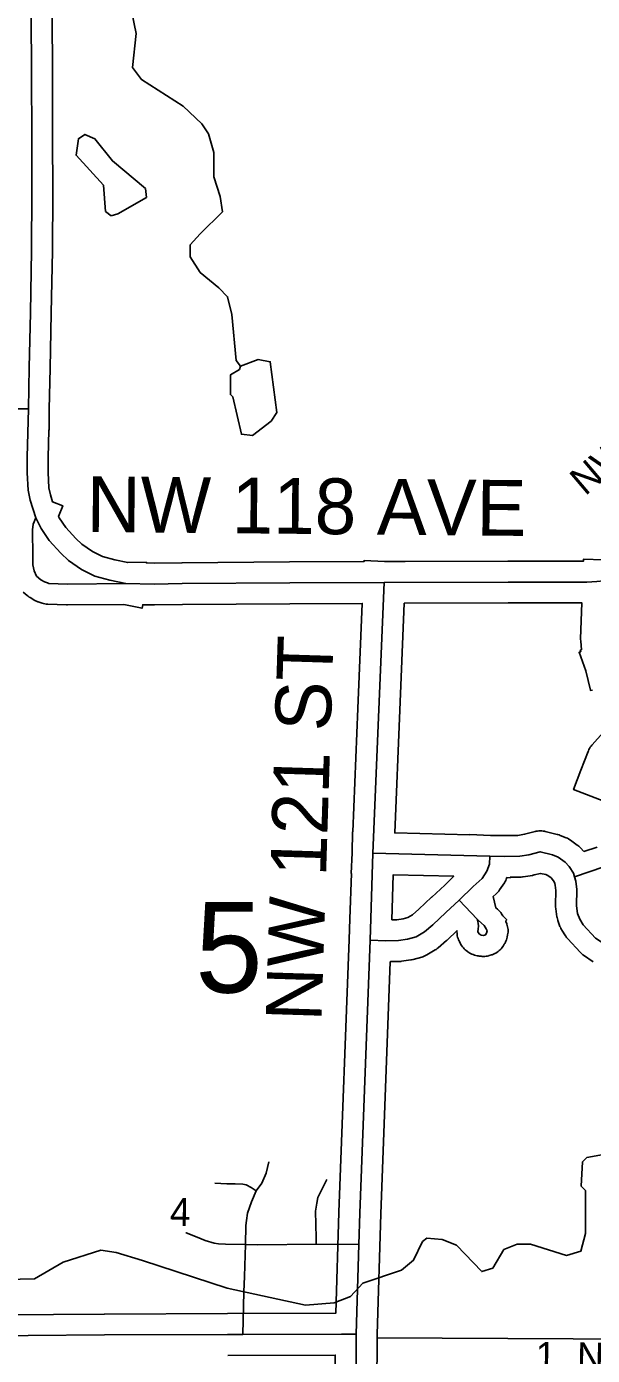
# Model space of a CAD drawing. Extents: x -1403959 to 81668, y -1400582 to 11018.
# Drawn here: x 6320.4 to 6398.9, y 9402.8 to 9587.1 of the extents above; entities that cross this region are included whole.
import ezdxf

# ---------------------------------------------------------------- set-up
doc = ezdxf.new("R2010")
doc.units = 0
for name, color, linetype in [('tdCiCityDivCarto', 7, 'Continuous'), ('tdCiCoBndryTxt', 7, 'Continuous'), ('tdCiMapFrame', 7, 'Continuous'), ('tdCiSectLine', 7, 'Continuous'), ('tdCoCityStreetMajor', 7, 'Continuous'), ('tdCoSectLinePart', 7, 'Continuous'), ('tdCoSectNmbr', 7, 'Continuous'), ('tdCoSurfBitum', 7, 'Continuous')]:
    doc.layers.add(name, color=color, linetype=linetype)

msp = doc.modelspace()

# ---------------------------------------------------------------- linework, layer by layer
at = {"layer": 'tdCiCityDivCarto'}
for points in [[(6350.39, 9405.67), (6350.55, 9411.6), (6350.62, 9413.72), (6350.76, 9418.15), (6350.8, 9420.78), (6350.9, 9421.49), (6351.06, 9422.48), (6351.59, 9424.08), (6352.27, 9425.6), (6353.04, 9426.67), (6353.65, 9428.03), (6354.01, 9429.62)], [(6346.51, 9426.68), (6348.18, 9426.59), (6349.35, 9426.56), (6350.39, 9426.53), (6350.85, 9426.41), (6351.56, 9426.08), (6352.27, 9425.6)], [(6360.57, 9418.2), (6360.56, 9419.07), (6360.5, 9422.79), (6360.66, 9423.88), (6360.82, 9424.68), (6361.21, 9425.5), (6362.06, 9427.17)], [(6342.5, 9419.79), (6342.53, 9419.78)], [(6342.53, 9419.78), (6344.05, 9419.17), (6345.18, 9418.72), (6346.42, 9418.34), (6347.03, 9418.25), (6348.02, 9418.18), (6350.76, 9418.15), (6352.5, 9418.11), (6360.57, 9418.2), (6366.5, 9418.14)], [(6366.5, 9418.14), (6366.5, 9418.14)]]:
    msp.add_lwpolyline(points, dxfattribs=at)
at = {"layer": 'tdCiCoBndryTxt'}
for points in [[(6320.66, 9534.06), (6320.78, 9539.8), (6320.94, 9547.4), (6321.1, 9556.04), (6321.15, 9564.12), (6321.13, 9571.78), (6321.08, 9580.54), (6321.07, 9588.81), (6321.02, 9596.89), (6321, 9605.18), (6320.94, 9612.41), (6320.93, 9620.6), (6320.88, 9625.81)], [(6283.73, 9534.18), (6285.98, 9534.14), (6290.69, 9534.12), (6295.74, 9534.12), (6299.22, 9534.12), (6307.92, 9534.1), (6318.4, 9534.08), (6320.66, 9534.06)], [(6334.16, 9509.85), (6331.96, 9510.31), (6329.88, 9510.87), (6328.05, 9511.81), (6326.25, 9513.05), (6325.18, 9514.07), (6323.56, 9515.82), (6322.44, 9517.47), (6321.68, 9518.94), (6320.9, 9521.4), (6320.62, 9522.78), (6320.52, 9525.2), (6320.52, 9527.36), (6320.66, 9534.06)], [(6370, 9510), (6387.18, 9510.05), (6398.08, 9510.05), (6399.48, 9510.15), (6400.45, 9510.23), (6401.63, 9510.33)], [(6334.16, 9509.85), (6338.12, 9509.77), (6342, 9509.84), (6356.9, 9509.95), (6370, 9510)], [(6365.81, 9287.33), (6365.81, 9288.16), (6365.85, 9307.72), (6365.85, 9307.83), (6365.94, 9330.42), (6365.96, 9349.37), (6365.95, 9356.26), (6365.95, 9356.34), (6365.95, 9356.35), (6365.95, 9356.43), (6366.01, 9382.59), (6366.13, 9405.71), (6366.5, 9418.14), (6366.63, 9422.52), (6368.05, 9460.36), (6368.45, 9472.42), (6369.27, 9492.38), (6370, 9510)], [(6368.05, 9460.36), (6370.21, 9460.29), (6371.99, 9460.31), (6373.24, 9460.5), (6374.45, 9460.83), (6375.61, 9461.52), (6376.77, 9462.51), (6378.57, 9464.22), (6380.4, 9465.91), (6382.36, 9467.83), (6383.59, 9468.95), (6384.25, 9469.95), (6384.61, 9470.92), (6384.66, 9472.01)], [(6368.45, 9472.42), (6384.66, 9472.01)], [(6384.66, 9472.01), (6386.65, 9471.99), (6388.8, 9472.01), (6390.08, 9472.23), (6391.65, 9472.63), (6393.32, 9472.23), (6394.13, 9471.9), (6395.08, 9471.2), (6395.65, 9470.58), (6396.25, 9469.68), (6396.41, 9469.15), (6400.46, 9470.53)], [(6396.41, 9469.15), (6396.58, 9468.58), (6396.73, 9467.39), (6396.66, 9465.15), (6396.82, 9464.07), (6397.11, 9463.29), (6397.59, 9462.52), (6399.3, 9460.66), (6400.62, 9459.75), (6401.35, 9459.47), (6402.36, 9459.25), (6405.48, 9459.21), (6413.56, 9458.89), (6425.02, 9458.71), (6427.02, 9458.71)], [(6382.9, 9463.28), (6383.03, 9462.75), (6383.06, 9462.3), (6383.04, 9461.93), (6382.99, 9461.54), (6383.16, 9461.23), (6383.44, 9461.05), (6383.76, 9461.02), (6384.05, 9461.1), (6384.21, 9461.36), (6384.27, 9461.66), (6384.16, 9461.96), (6383.86, 9462.43), (6383.09, 9463.08), (6382.9, 9463.28), (6380.4, 9465.91)], [(6253.17, 9405.01), (6257.36, 9405.04), (6266.29, 9405.11), (6287.87, 9405.26), (6310.01, 9405.46), (6331.21, 9405.6), (6348.29, 9405.66), (6350.39, 9405.67), (6364.08, 9405.73), (6366.13, 9405.71)]]:
    msp.add_lwpolyline(points, dxfattribs=at)
at = {"layer": 'tdCiMapFrame'}
for points in [[(6323.31, 9509.94), (6322.92, 9510.06), (6322.39, 9510.38), (6321.81, 9510.88), (6321.45, 9511.59), (6321.27, 9512.44), (6321.27, 9513.59), (6321.23, 9517.29), (6321.35, 9518.06), (6321.68, 9518.94)], [(6323.31, 9509.94), (6323.49, 9509.87), (6326.07, 9509.77), (6334.16, 9509.85)]]:
    msp.add_lwpolyline(points, dxfattribs=at)
at = {"layer": 'tdCiSectLine'}
for points in [[(6323.97, 9588.82), (6323.99, 9580.55), (6324.03, 9571.8), (6324.03, 9571.79), (6324.05, 9564.12), (6324.05, 9564.12), (6324.05, 9564.1), (6324, 9556.02), (6324, 9555.98), (6323.84, 9547.35), (6323.84, 9547.34), (6323.68, 9539.74), (6323.68, 9539.74), (6323.56, 9534.02), (6323.54, 9531.14), (6323.5, 9531.14), (6323.42, 9527.33), (6323.42, 9525.26), (6323.51, 9523.13), (6323.71, 9522.14), (6324.02, 9521.17), (6325.42, 9520.64), (6324.85, 9519.13), (6324.94, 9518.96), (6325.84, 9517.63), (6327.25, 9516.11), (6328.08, 9515.31), (6329.54, 9514.3), (6330.93, 9513.59), (6332.63, 9513.14), (6334.45, 9512.76), (6337.04, 9512.79), (6337.04, 9512.7), (6338.13, 9512.68), (6341.96, 9512.74), (6341.98, 9512.74), (6356.88, 9512.85), (6356.89, 9512.85), (6367.09, 9512.89), (6367.09, 9512.89), (6367.21, 9512.89), (6367.22, 9513.02), (6370.05, 9512.9), (6372.89, 9512.91), (6372.89, 9512.91), (6387.18, 9512.95), (6387.18, 9512.95), (6397.65, 9512.95), (6397.66, 9513.24), (6400.38, 9513.14)], [(6309.99, 9408.36), (6331.19, 9408.5), (6331.2, 9408.5), (6348.27, 9408.56), (6363.24, 9408.62), (6363.24, 9408.63), (6363.31, 9408.63), (6363.73, 9422.61), (6363.73, 9422.63), (6365.15, 9460.46), (6365.25, 9463.35), (6365.25, 9463.35), (6365.46, 9469.63), (6365.44, 9469.64), (6365.55, 9472.51), (6365.62, 9475.39), (6365.65, 9475.39), (6365.65, 9475.41), (6365.67, 9475.41), (6366.37, 9492.49), (6366.37, 9492.49), (6366.97, 9507.08), (6356.91, 9507.04), (6342.04, 9506.94), (6338.17, 9506.87), (6338.12, 9506.87), (6338.06, 9506.87), (6336.52, 9506.9), (6336.42, 9506.42), (6333.88, 9506.95), (6326.1, 9506.87), (6326.07, 9506.87), (6325.96, 9506.87), (6323.38, 9506.97), (6323.3, 9506.98), (6323.11, 9507), (6322.93, 9507.03), (6322.74, 9507.07), (6322.58, 9507.12), (6322, 9507.31), (6321.99, 9507.32), (6321.81, 9507.38), (6321.64, 9507.46), (6321.47, 9507.55), (6321.44, 9507.57), (6320.9, 9507.89), (6320.78, 9507.97), (6320.62, 9508.08), (6320.51, 9508.17), (6319.93, 9508.66)], [(6398.9, 9495.07), (6398.66, 9495.01), (6398.65, 9495.05), (6398.6, 9495.04), (6397.95, 9497.72), (6397.03, 9500.31), (6397.25, 9500.39), (6397.19, 9500.62), (6397.35, 9500.66), (6397.25, 9501.83), (6397.25, 9501.88), (6397.24, 9502.07), (6397.24, 9502.18), (6397.43, 9507.15), (6387.19, 9507.15), (6372.78, 9507.1), (6372.17, 9492.26), (6371.47, 9475.24), (6381.88, 9474.99), (6381.88, 9475.04), (6384.74, 9474.91), (6386.65, 9474.89), (6388.55, 9474.91), (6389.48, 9475.07), (6390.93, 9475.44), (6391.08, 9475.48), (6391.27, 9475.51), (6391.46, 9475.53), (6391.65, 9475.53), (6391.84, 9475.53), (6392.03, 9475.51), (6392.22, 9475.48), (6392.33, 9475.45), (6393.99, 9475.05), (6394.07, 9475.03), (6394.25, 9474.98), (6394.42, 9474.91), (6395.23, 9474.58), (6395.24, 9474.58), (6395.41, 9474.5), (6395.58, 9474.41), (6395.74, 9474.31), (6395.83, 9474.25), (6396.78, 9473.55), (6396.85, 9473.51), (6396.99, 9473.39), (6397.13, 9473.26), (6397.21, 9473.17), (6397.7, 9472.65)], [(6401.68, 9479.18), (6396.26, 9481.26), (6397.29, 9483.97), (6398.29, 9486.56), (6398.31, 9486.63), (6398.39, 9486.81), (6398.48, 9486.98), (6398.58, 9487.14), (6398.69, 9487.29), (6398.81, 9487.44), (6398.82, 9487.45), (6401.88, 9490.9)], [(6397.7, 9472.65), (6399.52, 9473.27)], [(6398.97, 9457.37), (6397.65, 9458.27), (6397.54, 9458.36), (6397.39, 9458.48), (6397.25, 9458.61), (6397.17, 9458.69), (6395.45, 9460.55), (6395.4, 9460.61), (6395.28, 9460.76), (6395.17, 9460.91), (6395.13, 9460.98), (6394.65, 9461.75), (6394.6, 9461.83), (6394.51, 9462), (6394.43, 9462.17), (6394.38, 9462.29), (6394.1, 9463.08), (6394.07, 9463.14), (6394.02, 9463.32), (6393.98, 9463.51), (6393.96, 9463.63), (6393.79, 9464.7), (6393.78, 9464.77), (6393.76, 9464.96), (6393.75, 9465.15), (6393.76, 9465.24), (6393.82, 9467.26), (6393.73, 9467.98), (6393.65, 9468.25), (6393.58, 9468.45), (6393.36, 9468.79), (6393.14, 9469.02), (6392.7, 9469.34), (6392.42, 9469.46), (6391.67, 9469.64), (6390.81, 9469.42), (6390.65, 9469.38), (6390.56, 9469.36), (6389.28, 9469.15), (6389.18, 9469.14), (6388.99, 9469.12), (6388.84, 9469.11), (6387.49, 9469.1), (6387.49, 9469.04), (6387.01, 9469.05), (6386.98, 9468.95), (6386.93, 9468.84), (6386.86, 9468.67), (6386.77, 9468.5), (6386.67, 9468.34), (6386, 9467.34), (6386, 9467.34), (6385.89, 9467.19), (6385.77, 9467.04), (6385.64, 9466.9), (6385.55, 9466.82), (6385.11, 9466.41), (6385.5, 9464.84), (6385.73, 9464.65), (6385.77, 9464.61), (6385.91, 9464.48), (6386.04, 9464.34), (6386.16, 9464.2), (6386.27, 9464.04), (6386.29, 9464.01), (6386.46, 9463.75), (6387, 9463.18), (6386.85, 9463.05), (6386.89, 9462.94), (6387, 9462.64), (6387.02, 9462.59), (6387.07, 9462.41), (6387.12, 9462.23), (6387.15, 9462.04), (6387.17, 9461.85), (6387.17, 9461.66), (6387.17, 9461.47), (6387.15, 9461.28), (6387.12, 9461.09), (6387.12, 9461.09), (6387.06, 9460.79), (6387.01, 9460.61), (6386.96, 9460.43), (6386.89, 9460.25), (6386.81, 9460.08), (6386.72, 9459.91), (6386.66, 9459.81), (6386.49, 9459.54), (6386.46, 9459.49), (6386.35, 9459.34), (6386.23, 9459.19), (6386.1, 9459.05), (6385.96, 9458.92), (6385.81, 9458.8), (6385.66, 9458.69), (6385.5, 9458.59), (6385.33, 9458.5), (6385.16, 9458.42), (6384.98, 9458.35), (6384.86, 9458.32), (6384.57, 9458.23), (6384.51, 9458.22), (6384.33, 9458.17), (6384.14, 9458.14), (6383.95, 9458.12), (6383.76, 9458.12), (6383.57, 9458.12), (6383.44, 9458.13), (6383.12, 9458.17), (6383.06, 9458.18), (6382.88, 9458.21), (6382.69, 9458.25), (6382.51, 9458.31), (6382.33, 9458.37), (6382.16, 9458.45), (6381.99, 9458.54), (6381.9, 9458.59), (6381.62, 9458.77), (6381.54, 9458.82), (6381.39, 9458.93), (6381.24, 9459.05), (6381.1, 9459.18), (6380.98, 9459.32), (6380.85, 9459.47), (6380.74, 9459.62), (6380.64, 9459.78), (6380.6, 9459.86), (6380.44, 9460.17), (6380.39, 9460.26), (6380.31, 9460.43), (6380.24, 9460.61), (6380.19, 9460.79), (6380.14, 9460.97), (6380.11, 9461.16), (6380.1, 9461.35), (6380.09, 9461.54), (6380.09, 9461.67), (6378.76, 9460.41), (6378.68, 9460.33), (6378.66, 9460.31), (6377.5, 9459.31), (6377.37, 9459.21), (6377.22, 9459.1), (6377.09, 9459.02), (6375.92, 9458.33), (6375.9, 9458.32), (6375.73, 9458.23), (6375.56, 9458.15), (6375.38, 9458.08), (6375.21, 9458.03), (6374.01, 9457.7), (6374, 9457.7), (6373.81, 9457.66), (6373.68, 9457.63), (6372.42, 9457.44), (6372.37, 9457.43), (6372.18, 9457.42), (6372.03, 9457.41), (6370.86, 9457.39), (6370.86, 9457.36), (6370.84, 9457.36), (6369.53, 9422.42), (6369.03, 9405.66), (6368.91, 9382.58)], [(6371.05, 9463.2), (6371.75, 9463.21), (6372.64, 9463.35), (6373.3, 9463.53), (6373.91, 9463.88), (6374.82, 9464.67), (6376.57, 9466.33), (6376.6, 9466.35), (6378.4, 9468.01), (6379.65, 9469.24), (6371.26, 9469.44), (6371.05, 9463.2)], [(6363.1, 9382.6), (6363.21, 9402.82), (6348.3, 9402.76)]]:
    msp.add_lwpolyline(points, dxfattribs=at)
at = {"layer": 'tdCoCityStreetMajor'}
msp.add_lwpolyline([(6368.99, 9405.2), (6414.36, 9404.98)], dxfattribs=at)
at = {"layer": 'tdCoSurfBitum'}
for points in [[(6334.99, 9589.07), (6335.59, 9586.17), (6335.11, 9581.44), (6336.33, 9579.76), (6342.12, 9576.07), (6344.7, 9573.62), (6345.62, 9572.24), (6346.37, 9569.64), (6346.36, 9566.28), (6347.26, 9563.53), (6347.56, 9561.39), (6344.5, 9558.35), (6343.12, 9556.83), (6343.11, 9555.15), (6344.48, 9553.01), (6347.07, 9550.86), (6348.28, 9549.64), (6348.89, 9547.19), (6349.47, 9540.78), (6350.08, 9540.01), (6352.53, 9540.92), (6354.21, 9540.61), (6355.1, 9533.58), (6354.33, 9532.36), (6351.73, 9530.39), (6350.2, 9530.55), (6349, 9535.74), (6348.69, 9536.05), (6348.7, 9538.8), (6349.93, 9539.56), (6350.08, 9540.01)], [(6332.14, 9560.84), (6331.38, 9561.46), (6331.08, 9565.12), (6327.28, 9569.26), (6327.6, 9571.55), (6328.51, 9572.15), (6329.89, 9571.54), (6332.32, 9568.47), (6336.89, 9564.64), (6337.03, 9563.42), (6333.06, 9561.14), (6332.14, 9560.84)], [(6402.22, 9430.97), (6398.1, 9430.22), (6397.48, 9429.61), (6397.32, 9426.26), (6397.93, 9425.64), (6397.91, 9419.69), (6397.29, 9417.25), (6395.3, 9416.65), (6390.27, 9418.19), (6388.43, 9418.2), (6386.6, 9417.44), (6385.06, 9414.85), (6383.53, 9414.4), (6380.03, 9418.08), (6378.05, 9418.85), (6375.92, 9419.01), (6375.3, 9418.55), (6374.07, 9415.96), (6372.39, 9414.6), (6367.04, 9412.78), (6365.35, 9410.96), (6363.06, 9410.05), (6359.09, 9409.76), (6348.25, 9412.09), (6336.51, 9415.95), (6332.85, 9417.03), (6330.71, 9417.35), (6325.51, 9415.69), (6321.53, 9413.41), (6317.56, 9413.28)]]:
    msp.add_lwpolyline(points, dxfattribs=at)

# ---------------------------------------------------------------- texts
at = {"layer": 'tdCoSectLinePart'}
msp.add_text('5', height=12.57, rotation=359.9891, dxfattribs=at).set_placement((6343.8, 9453.1))
at = {"layer": 'tdCoSectNmbr'}
for s, height, rotation, p in [('NW JESTER', 3.869, 40.3149, (6397.86, 9521.92)), ('NW 118 AVE', 7.738, 359.4707, (6328.72, 9517.01)), ('NW 121 ST', 7.738, 88.195, (6361.3, 9449.04)), ('4', 3.87, 359.2411, (6340.26, 9420.75)), ('1. NW 108TH CT', 3.8691, 359.2411, (6390.96, 9400.78))]:
    msp.add_text(s, height=height, rotation=rotation, dxfattribs=at).set_placement(p)

doc.saveas('drawing.dxf')
